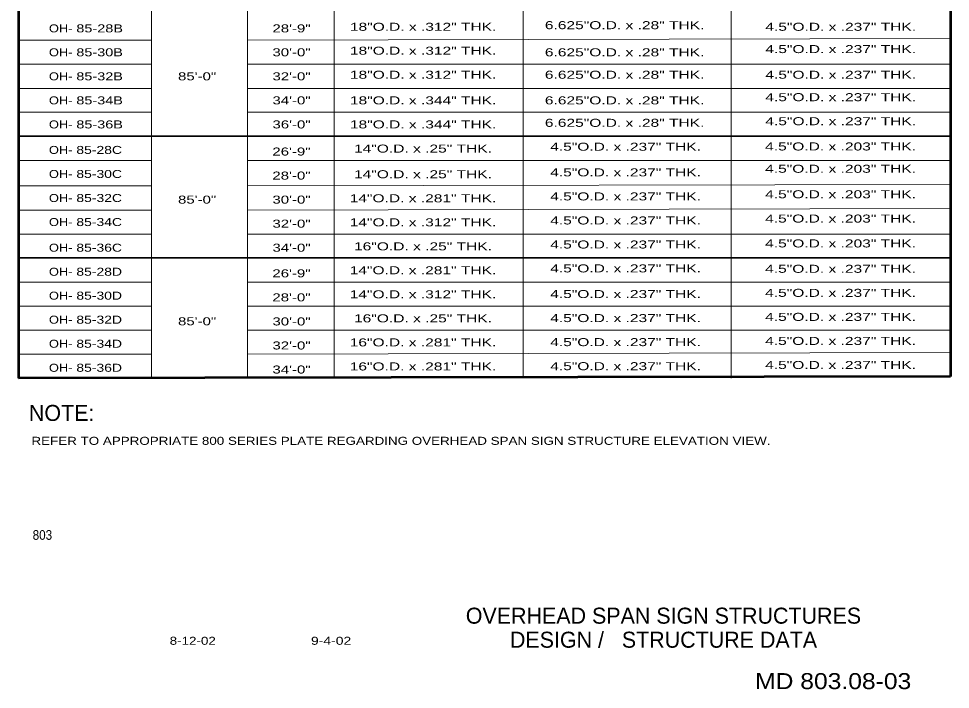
# Model space of a CAD drawing. Extents: x -34832.9 to -34825.9, y -181503 to -181493.
# Drawn here: x -34832.9 to -34825.93, y -181503.03 to -181498.01 of the extents above; entities that cross this region are included whole.
import ezdxf
from ezdxf.enums import TextEntityAlignment as Align

# ---------------------------------------------------------------- set-up
doc = ezdxf.new("R2010")
doc.units = 0
doc.header["$LTSCALE"] = 0.024
doc.layers.add('1', color=7, linetype='Continuous', lineweight=13)
doc.layers.add('12', color=7, linetype='Continuous')
doc.layers.add('13', color=7, linetype='Continuous')

msp = doc.modelspace()

# ---------------------------------------------------------------- linework, layer by layer
at = {"layer": '1', "lineweight": 53}
for p, q in [((-34832.903, -181492.988), (-34832.903, -181500.697)), ((-34825.926, -181492.988), (-34825.926, -181500.685)), ((-34825.926, -181500.685), (-34832.903, -181500.697))]:
    msp.add_line(p, q, dxfattribs=at)
at = {"layer": '1'}
for p, q in [((-34831.908, -181492.988), (-34831.908, -181500.697)), ((-34831.189, -181492.988), (-34831.189, -181500.697)), ((-34830.541, -181492.988), (-34830.541, -181500.697)), ((-34829.126, -181492.988), (-34829.126, -181500.697)), ((-34827.568, -181492.988), (-34827.568, -181500.697)), ((-34831.908, -181498.167), (-34832.903, -181498.167)), ((-34825.926, -181498.155), (-34831.189, -181498.167)), ((-34831.908, -181498.347), (-34832.903, -181498.347)), ((-34825.926, -181498.347), (-34831.189, -181498.347)), ((-34831.908, -181498.527), (-34832.903, -181498.527)), ((-34825.926, -181498.527), (-34831.189, -181498.527)), ((-34831.908, -181498.706), (-34832.903, -181498.706)), ((-34825.926, -181498.706), (-34831.189, -181498.706)), ((-34831.908, -181499.066), (-34832.903, -181499.066)), ((-34825.926, -181499.066), (-34831.189, -181499.066)), ((-34831.908, -181499.258), (-34832.903, -181499.258)), ((-34825.926, -181499.246), (-34831.189, -181499.258)), ((-34831.908, -181499.438), (-34832.903, -181499.438)), ((-34825.926, -181499.426), (-34831.189, -181499.438)), ((-34831.908, -181499.618), (-34832.903, -181499.618)), ((-34825.926, -181499.618), (-34831.189, -181499.618)), ((-34831.908, -181499.977), (-34832.903, -181499.977)), ((-34825.926, -181499.977), (-34831.189, -181499.977)), ((-34831.908, -181500.157), (-34832.903, -181500.157)), ((-34825.926, -181500.157), (-34831.189, -181500.157)), ((-34831.908, -181500.337), (-34832.903, -181500.337)), ((-34825.926, -181500.337), (-34831.189, -181500.337)), ((-34825.926, -181500.505), (-34831.189, -181500.517)), ((-34831.908, -181500.517), (-34832.903, -181500.517))]:
    msp.add_line(p, q, dxfattribs=at)
at = {"layer": '1', "lineweight": 35}
for p, q in [((-34825.926, -181498.886), (-34832.903, -181498.886)), ((-34825.926, -181499.797), (-34832.903, -181499.797))]:
    msp.add_line(p, q, dxfattribs=at)

# ---------------------------------------------------------------- texts
at = {"layer": '12'}
msp.add_text('NOTE:', height=0.12, dxfattribs=at).set_placement((-34832.581, -181501.017), align=Align.CENTER)
at = {"layer": '13'}
for s, height, width, p in [('OH-', 0.05992, 1.2, (-34832.588, -181498.108)), ('28\'-9"', 0.05992, 1.4, (-34830.8595, -181498.108)), ('18"O.D. x .312" THK.', 0.05992, 1.45, (-34829.874, -181498.096)), ('6.625"O.D. x .28" THK.', 0.06, 1.45, (-34828.365, -181498.084)), ('4.5"O.D. x .237" THK.', 0.05992, 1.45, (-34826.747, -181498.096)), ('4.5"O.D. x .237" THK.', 0.05992, 1.45, (-34826.747, -181498.263)), ('OH-', 0.05992, 1.2, (-34832.588, -181498.287)), ('30\'-0"', 0.05992, 1.4, (-34830.8595, -181498.287)), ('18"O.D. x .312" THK.', 0.05992, 1.45, (-34829.874, -181498.275)), ('6.625"O.D. x .28" THK.', 0.06, 1.45, (-34828.365, -181498.287)), ('OH-', 0.05992, 1.2, (-34832.588, -181498.467)), ('85\'-0"', 0.05992, 1.4, (-34831.5665, -181498.467)), ('32\'-0"', 0.05992, 1.4, (-34830.8595, -181498.467)), ('18"O.D. x .312" THK.', 0.05992, 1.45, (-34829.874, -181498.455)), ('6.625"O.D. x .28" THK.', 0.06, 1.45, (-34828.365, -181498.455)), ('4.5"O.D. x .237" THK.', 0.05992, 1.45, (-34826.747, -181498.455)), ('OH-', 0.05992, 1.2, (-34832.588, -181498.647)), ('34\'-0"', 0.05992, 1.4, (-34830.8595, -181498.647)), ('18"O.D. x .344" THK.', 0.05992, 1.45, (-34829.874, -181498.647)), ('6.625"O.D. x .28" THK.', 0.06, 1.45, (-34828.365, -181498.647)), ('4.5"O.D. x .237" THK.', 0.05992, 1.45, (-34826.747, -181498.623)), ('OH-', 0.05992, 1.2, (-34832.588, -181498.827)), ('36\'-0"', 0.05992, 1.4, (-34830.8595, -181498.827)), ('18"O.D. x .344" THK.', 0.05992, 1.45, (-34829.874, -181498.827)), ('6.625"O.D. x .28" THK.', 0.06, 1.45, (-34828.365, -181498.815)), ('4.5"O.D. x .237" THK.', 0.05992, 1.45, (-34826.747, -181498.803)), ('OH-', 0.05992, 1.2, (-34832.588, -181499.018)), ('26\'-9"', 0.06, 1.4, (-34830.86, -181499.03)), ('14"O.D. x .25" THK.', 0.06, 1.45, (-34829.875, -181499.008)), ('4.5"O.D. x .237" THK.', 0.05992, 1.45, (-34828.358, -181498.994)), ('4.5"O.D. x .203" THK.', 0.06, 1.45, (-34826.748, -181498.992)), ('4.5"O.D. x .203" THK.', 0.06, 1.45, (-34826.748, -181499.159)), ('OH-', 0.05992, 1.2, (-34832.588, -181499.198)), ('28\'-0"', 0.06, 1.4, (-34830.86, -181499.21)), ('14"O.D. x .25" THK.', 0.06, 1.45, (-34829.875, -181499.2)), ('4.5"O.D. x .237" THK.', 0.05992, 1.45, (-34828.358, -181499.186)), ('OH-', 0.05992, 1.2, (-34832.588, -181499.378)), ('14"O.D. x .281" THK.', 0.06, 1.45, (-34829.875, -181499.38)), ('4.5"O.D. x .237" THK.', 0.05992, 1.45, (-34828.358, -181499.366)), ('4.5"O.D. x .203" THK.', 0.06, 1.45, (-34826.748, -181499.35)), ('85\'-0"', 0.05992, 1.4, (-34831.5665, -181499.39)), ('30\'-0"', 0.05992, 1.4, (-34830.8595, -181499.39)), ('OH-', 0.05992, 1.2, (-34832.588, -181499.558)), ('32\'-0"', 0.05992, 1.4, (-34830.8595, -181499.57)), ('14"O.D. x .312" THK.', 0.06, 1.45, (-34829.875, -181499.56)), ('4.5"O.D. x .237" THK.', 0.05992, 1.45, (-34828.358, -181499.546)), ('4.5"O.D. x .203" THK.', 0.06, 1.45, (-34826.748, -181499.532)), ('4.5"O.D. x .237" THK.', 0.05992, 1.45, (-34828.358, -181499.726)), ('4.5"O.D. x .203" THK.', 0.06, 1.45, (-34826.748, -181499.718)), ('OH-', 0.05992, 1.2, (-34832.588, -181499.75)), ('34\'-0"', 0.05992, 1.4, (-34830.8595, -181499.75)), ('16"O.D. x .25" THK.', 0.06, 1.45, (-34829.875, -181499.74)), ('OH-', 0.05992, 1.2, (-34832.588, -181499.93)), ('26\'-9"', 0.06, 1.4, (-34830.86, -181499.942)), ('14"O.D. x .281" THK.', 0.06, 1.45, (-34829.875, -181499.919)), ('4.5"O.D. x .237" THK.', 0.05992, 1.45, (-34828.358, -181499.905)), ('4.5"O.D. x .237" THK.', 0.06, 1.45, (-34826.748, -181499.908)), ('OH-', 0.05992, 1.2, (-34832.588, -181500.109)), ('28\'-0"', 0.06, 1.4, (-34830.86, -181500.122)), ('14"O.D. x .312" THK.', 0.06, 1.45, (-34829.875, -181500.099)), ('4.5"O.D. x .237" THK.', 0.05992, 1.45, (-34828.358, -181500.097)), ('4.5"O.D. x .237" THK.', 0.06, 1.45, (-34826.748, -181500.088)), ('OH-', 0.05992, 1.2, (-34832.588, -181500.289)), ('16"O.D. x .25" THK.', 0.06, 1.45, (-34829.875, -181500.279)), ('4.5"O.D. x .237" THK.', 0.05992, 1.45, (-34828.358, -181500.277)), ('4.5"O.D. x .237" THK.', 0.06, 1.45, (-34826.748, -181500.268)), ('85\'-0"', 0.05992, 1.4, (-34831.5665, -181500.301)), ('30\'-0"', 0.05992, 1.4, (-34830.8595, -181500.302)), ('OH-', 0.05992, 1.2, (-34832.588, -181500.469)), ('32\'-0"', 0.05992, 1.4, (-34830.8595, -181500.482)), ('16"O.D. x .281" THK.', 0.06, 1.45, (-34829.875, -181500.459)), ('4.5"O.D. x .237" THK.', 0.05992, 1.45, (-34828.358, -181500.457)), ('4.5"O.D. x .237" THK.', 0.06, 1.45, (-34826.748, -181500.448)), ('16"O.D. x .281" THK.', 0.06, 1.45, (-34829.875, -181500.639)), ('4.5"O.D. x .237" THK.', 0.05992, 1.45, (-34828.358, -181500.637)), ('4.5"O.D. x .237" THK.', 0.06, 1.45, (-34826.748, -181500.628)), ('OH-', 0.05992, 1.2, (-34832.588, -181500.649)), ('34\'-0"', 0.05992, 1.4, (-34830.8595, -181500.662)), ('REFER TO APPROPRIATE 800 SERIES PLATE REGARDING OVERHEAD SPAN SIGN STRUCTURE ELEVATION VIEW.', 0.06, 1.25, (-34830.04, -181501.196)), ('803', 0.07251, 0.9, (-34832.725, -181501.907)), ('MD 803.08-03', 0.12, 1.15, (-34826.8035, -181503.025))]:
    msp.add_text(s, height=height, dxfattribs=dict(at, width=width)).set_placement(p, align=Align.CENTER)
for s, height, width, p in [('85-28B', 0.06, 1.35, (-34832.471, -181498.108)), ('85-30B', 0.05992, 1.35, (-34832.471, -181498.287)), ('85-32B', 0.05992, 1.35, (-34832.471, -181498.467)), ('85-34B', 0.05992, 1.35, (-34832.471, -181498.647)), ('85-36B', 0.05992, 1.35, (-34832.471, -181498.827)), ('85-28C', 0.06, 1.3, (-34832.471, -181499.018)), ('85-30C', 0.06, 1.3, (-34832.471, -181499.198)), ('85-32C', 0.06, 1.3, (-34832.471, -181499.378)), ('85-34C', 0.06, 1.3, (-34832.471, -181499.558)), ('85-36C', 0.06, 1.3, (-34832.471, -181499.75)), ('85-28D', 0.06, 1.3, (-34832.471, -181499.93)), ('85-30D', 0.06, 1.3, (-34832.471, -181500.109)), ('85-32D', 0.06, 1.3, (-34832.471, -181500.289)), ('85-34D', 0.06, 1.3, (-34832.471, -181500.469)), ('85-36D', 0.06, 1.3, (-34832.471, -181500.649)), ('8-12-02', 0.06, 1.25, (-34831.772, -181502.693)), ('9-4-02', 0.06, 1.3, (-34830.714, -181502.693))]:
    msp.add_text(s, height=height, dxfattribs=dict(at, width=width)).set_placement(p)
for s, p in [('OVERHEAD SPAN SIGN STRUCTURES', (-34828.0745, -181502.535)), ('DESIGN /   STRUCTURE DATA', (-34828.074, -181502.715))]:
    msp.add_text(s, height=0.12, dxfattribs=at).set_placement(p, align=Align.CENTER)

doc.saveas('drawing.dxf')
